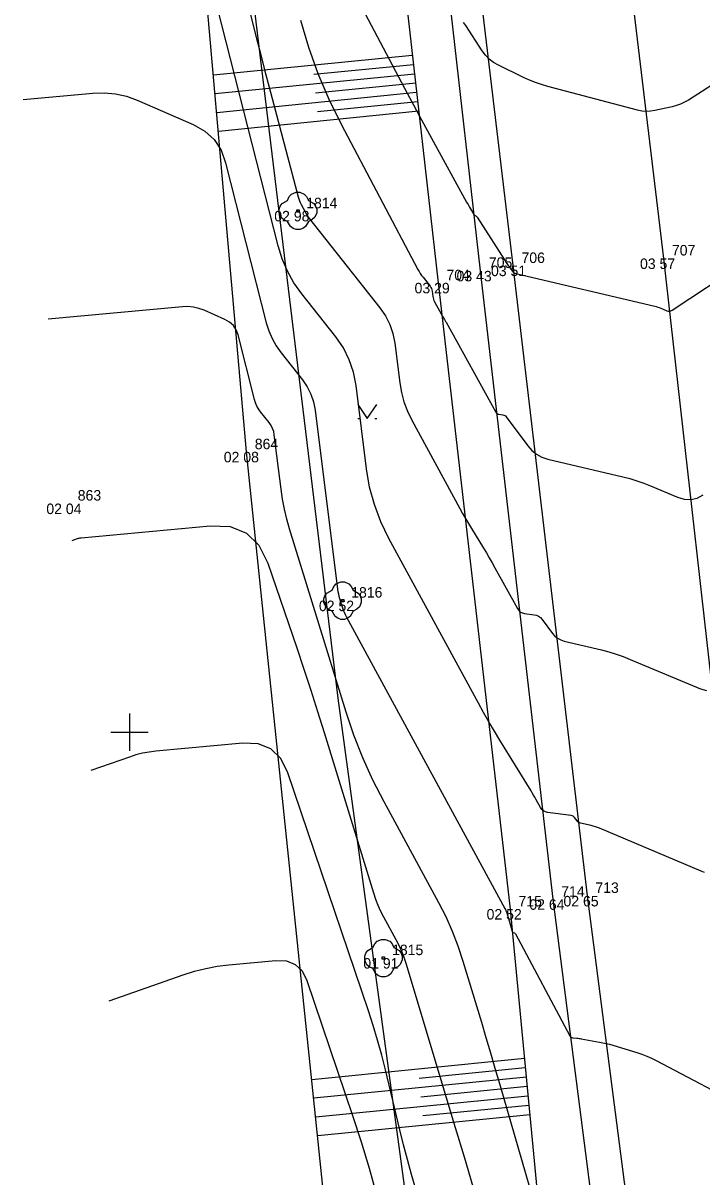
# Model space of a CAD drawing. Extents: x -711234 to -710007, y -1026313 to -1025448.
# Drawn here: x -710902.84 to -710884.74, y -1026086.87 to -1026056.08 of the extents above; entities that cross this region are included whole.
import ezdxf

# ---------------------------------------------------------------- set-up
doc = ezdxf.new("R2010")
doc.units = 0
for name, color, linetype in [('Ex_Major Contours', 7, 'Continuous'), ('Ex_Minor Contours', 7, 'Continuous'), ('Z_body', 7, 'Continuous'), ('Z_body_cisla', 7, 'Continuous'), ('Z_body_vysky_redukovane', 7, 'Continuous'), ('Z_hektometricka_sit', 7, 'Continuous'), ('Z_hrany_paty', 7, 'Continuous'), ('Z_katastr_hranice', 7, 'Continuous'), ('Z_komunikace', 7, 'Continuous'), ('Z_komunikace_osa', 7, 'Continuous'), ('Z_pole_rozhranni', 7, 'Continuous'), ('Z_technicke_srafy', 7, 'Continuous'), ('Z_vdz12_plna', 7, 'Continuous'), ('Z_zelen_jednotliva', 7, 'Continuous'), ('Z_znaky_kultur', 7, 'Continuous')]:
    doc.layers.add(name, color=color, linetype=linetype)

# ---------------------------------------------------------------- blocks, each defined once
blk = doc.blocks.new('POINT_DISPLAY')
blk.add_line((0, 0), (0, 0))
blk = doc.blocks.new('Z24')
for p, q in [((-0.28, 0.28), (-0.23, 0.38)), ((-0.23, 0.38), (-0.17, 0.45)), ((-0.17, 0.45), (-0.05, 0.5)), ((-0.05, 0.5), (0.05, 0.5)), ((0.05, 0.5), (0.17, 0.45)), ((0.17, 0.45), (0.23, 0.38)), ((0.23, 0.38), (0.28, 0.28)), ((-0.5, 0.05), (-0.47, 0.13)), ((-0.5, -0.05), (-0.5, 0.05)), ((-0.47, 0.13), (-0.42, 0.2)), ((-0.42, 0.2), (-0.28, 0.28)), ((-0.03, -0.03), (-0.03, 0.03)), ((-0.03, 0.03), (0.03, 0.03)), ((0.03, 0.03), (0.03, -0.03)), ((0.28, 0.28), (0.42, 0.2)), ((0.42, 0.2), (0.47, 0.13)), ((0.47, 0.13), (0.5, 0.05)), ((0.5, 0.05), (0.5, -0.05)), ((-0.45, -0.17), (-0.5, -0.05)), ((-0.38, -0.23), (-0.45, -0.17)), ((-0.28, -0.28), (-0.38, -0.23)), ((-0.2, -0.42), (-0.28, -0.28)), ((0.03, -0.03), (-0.03, -0.03)), ((0.28, -0.28), (0.2, -0.42)), ((0.38, -0.23), (0.28, -0.28)), ((0.45, -0.17), (0.38, -0.23)), ((0.5, -0.05), (0.45, -0.17)), ((-0.13, -0.47), (-0.2, -0.42)), ((-0.05, -0.5), (-0.13, -0.47)), ((0.05, -0.5), (-0.05, -0.5)), ((0.13, -0.47), (0.05, -0.5)), ((0.2, -0.42), (0.13, -0.47))]:
    blk.add_line(p, q)
blk = doc.blocks.new('Z314')
for p, q in [((-0.25, 0.17), (0, -0.2)), ((0, -0.2), (0.25, 0.17)), ((-0.25, -0.2), (-0.2, -0.2)), ((0.2, -0.2), (0.25, -0.2))]:
    blk.add_line(p, q)

msp = doc.modelspace()

# ---------------------------------------------------------------- linework, layer by layer
at = {"layer": 'Ex_Major Contours'}
for points in [[(-710898.331, -1026049.709), (-710896.61, -1026056.491), (-710896.5, -1026056.925), (-710896.388, -1026057.358), (-710896.275, -1026057.791), (-710896.162, -1026058.224), (-710895.505, -1026060.713), (-710895.489, -1026060.766), (-710895.471, -1026060.818), (-710895.449, -1026060.869), (-710895.425, -1026060.919), (-710895.321, -1026061.116), (-710895.294, -1026061.164), (-710895.264, -1026061.211), (-710895.233, -1026061.257), (-710895.2, -1026061.301), (-710893.325, -1026063.673), (-710893.176, -1026063.889), (-710893.061, -1026064.119), (-710892.978, -1026064.362), (-710892.929, -1026064.619), (-710892.796, -1026065.676), (-710892.752, -1026065.936), (-710892.683, -1026066.189), (-710892.592, -1026066.434), (-710892.476, -1026066.672), (-710891.193, -1026069.034), (-710891.119, -1026069.168), (-710891.043, -1026069.301), (-710890.966, -1026069.434), (-710890.886, -1026069.565), (-710890.565, -1026070.088), (-710890.486, -1026070.219), (-710890.408, -1026070.351), (-710890.331, -1026070.484), (-710890.257, -1026070.618), (-710889.657, -1026071.704), (-710889.621, -1026071.755), (-710889.578, -1026071.794), (-710889.526, -1026071.82), (-710889.465, -1026071.835), (-710889.208, -1026071.869), (-710889.146, -1026071.882), (-710889.092, -1026071.907), (-710889.043, -1026071.943), (-710889.002, -1026071.99), (-710888.724, -1026072.365), (-710888.66, -1026072.438), (-710888.587, -1026072.496), (-710888.504, -1026072.54), (-710888.412, -1026072.57), (-710887.419, -1026072.805), (-710887.223, -1026072.856), (-710887.029, -1026072.915), (-710886.838, -1026072.982), (-710886.649, -1026073.057), (-710884.78, -1026073.844), (-710884.62, -1026073.892)], [(-710901.531, -1026069.883), (-710901.388, -1026069.833), (-710901.364, -1026069.825), (-710901.34, -1026069.819), (-710901.315, -1026069.814), (-710901.291, -1026069.811), (-710897.85, -1026069.492), (-710897.317, -1026069.514), (-710896.883, -1026069.688), (-710896.548, -1026070.013), (-710896.311, -1026070.491), (-710895.543, -1026072.754), (-710895.355, -1026073.317), (-710895.17, -1026073.88), (-710894.99, -1026074.445), (-710894.813, -1026075.011), (-710893.493, -1026079.292), (-710893.438, -1026079.456), (-710893.375, -1026079.616), (-710893.304, -1026079.773), (-710893.226, -1026079.926), (-710892.896, -1026080.533), (-710892.818, -1026080.687), (-710892.748, -1026080.844), (-710892.686, -1026081.004), (-710892.632, -1026081.168), (-710891.315, -1026085.55), (-710891.08, -1026086.336), (-710890.846, -1026087.122)]]:
    msp.add_lwpolyline(points, dxfattribs=at)
at = {"layer": 'Ex_Minor Contours'}
for points in [[(-710884.667, -1026078.749), (-710884.758, -1026078.709), (-710887.471, -1026077.566), (-710887.525, -1026077.545), (-710887.58, -1026077.526), (-710887.635, -1026077.509), (-710887.691, -1026077.494), (-710887.975, -1026077.427), (-710888.001, -1026077.419), (-710888.025, -1026077.406), (-710888.046, -1026077.389), (-710888.064, -1026077.369), (-710888.132, -1026077.277), (-710888.15, -1026077.257), (-710888.171, -1026077.241), (-710888.195, -1026077.23), (-710888.222, -1026077.224), (-710888.853, -1026077.142), (-710888.913, -1026077.127), (-710888.964, -1026077.101), (-710889.007, -1026077.063), (-710889.042, -1026077.013), (-710889.166, -1026076.788), (-710889.197, -1026076.732), (-710889.229, -1026076.677), (-710889.262, -1026076.622), (-710889.295, -1026076.567), (-710890.125, -1026075.216), (-710890.272, -1026074.971), (-710890.417, -1026074.725), (-710890.558, -1026074.477), (-710890.696, -1026074.227), (-710893.085, -1026069.828), (-710893.3, -1026069.386), (-710893.471, -1026068.929), (-710893.598, -1026068.458), (-710893.681, -1026067.973), (-710893.96, -1026065.747), (-710894.028, -1026065.394), (-710894.141, -1026065.061), (-710894.299, -1026064.746), (-710894.503, -1026064.45), (-710895.408, -1026063.306), (-710895.617, -1026063.011), (-710895.792, -1026062.7), (-710895.933, -1026062.371), (-710896.04, -1026062.026), (-710897.768, -1026055.213)], [(-710894.049, -1026055.203), (-710892.59, -1026057.964), (-710892.432, -1026058.262), (-710892.273, -1026058.559), (-710892.112, -1026058.855), (-710891.95, -1026059.151), (-710891.012, -1026060.854), (-710890.994, -1026060.888), (-710890.975, -1026060.921), (-710890.956, -1026060.955), (-710890.936, -1026060.988), (-710890.831, -1026061.168), (-710890.825, -1026061.177), (-710890.818, -1026061.186), (-710890.81, -1026061.193), (-710890.802, -1026061.2), (-710890.765, -1026061.226), (-710890.756, -1026061.233), (-710890.748, -1026061.241), (-710890.741, -1026061.249), (-710890.734, -1026061.258), (-710889.919, -1026062.521), (-710889.904, -1026062.544), (-710889.888, -1026062.567), (-710889.872, -1026062.59), (-710889.856, -1026062.612), (-710889.79, -1026062.701), (-710889.772, -1026062.721), (-710889.752, -1026062.738), (-710889.729, -1026062.75), (-710889.703, -1026062.758), (-710885.998, -1026063.635), (-710885.957, -1026063.645), (-710885.916, -1026063.658), (-710885.876, -1026063.672), (-710885.836, -1026063.687), (-710885.679, -1026063.754), (-710885.64, -1026063.765), (-710885.602, -1026063.767), (-710885.565, -1026063.758), (-710885.529, -1026063.74), (-710883.678, -1026062.513)], [(-710895.441, -1026056.001), (-710895.23, -1026056.719), (-710894.979, -1026057.421), (-710894.688, -1026058.108), (-710894.357, -1026058.78), (-710892.312, -1026062.65), (-710892.281, -1026062.706), (-710892.248, -1026062.759), (-710892.212, -1026062.811), (-710892.174, -1026062.861), (-710891.984, -1026063.101), (-710891.964, -1026063.131), (-710891.948, -1026063.163), (-710891.937, -1026063.196), (-710891.93, -1026063.232), (-710891.912, -1026063.378), (-710891.905, -1026063.414), (-710891.896, -1026063.448), (-710891.883, -1026063.482), (-710891.867, -1026063.515), (-710891.69, -1026063.841), (-710891.68, -1026063.859), (-710891.67, -1026063.878), (-710891.659, -1026063.896), (-710891.648, -1026063.914), (-710891.604, -1026063.986), (-710891.593, -1026064.004), (-710891.582, -1026064.023), (-710891.572, -1026064.041), (-710891.561, -1026064.059), (-710890.234, -1026066.463), (-710890.219, -1026066.485), (-710890.201, -1026066.501), (-710890.179, -1026066.512), (-710890.154, -1026066.518), (-710890.046, -1026066.532), (-710890.021, -1026066.538), (-710889.998, -1026066.548), (-710889.977, -1026066.563), (-710889.96, -1026066.583), (-710889.384, -1026067.361), (-710889.275, -1026067.486), (-710889.149, -1026067.586), (-710889.008, -1026067.662), (-710888.85, -1026067.714), (-710886.85, -1026068.187), (-710886.661, -1026068.235), (-710886.475, -1026068.292), (-710886.291, -1026068.356), (-710886.109, -1026068.428), (-710885.388, -1026068.732), (-710885.21, -1026068.785), (-710885.037, -1026068.792), (-710884.867, -1026068.753), (-710884.702, -1026068.668)], [(-710882.762, -1026056.634), (-710885.098, -1026058.131), (-710885.201, -1026058.19), (-710885.307, -1026058.24), (-710885.417, -1026058.28), (-710885.531, -1026058.311), (-710885.996, -1026058.413), (-710886.113, -1026058.431), (-710886.228, -1026058.436), (-710886.344, -1026058.426), (-710886.459, -1026058.403), (-710888.846, -1026057.769), (-710889.013, -1026057.721), (-710889.177, -1026057.664), (-710889.338, -1026057.6), (-710889.496, -1026057.527), (-710890.166, -1026057.202), (-710890.295, -1026057.128), (-710890.41, -1026057.04), (-710890.512, -1026056.936), (-710890.6, -1026056.817), (-710891.034, -1026056.145), (-710891.064, -1026056.103), (-710891.097, -1026056.065)], [(-710902.837, -1026058.116), (-710900.981, -1026057.946), (-710900.674, -1026057.937), (-710900.374, -1026057.965), (-710900.08, -1026058.032), (-710899.792, -1026058.137), (-710898.306, -1026058.783), (-710897.994, -1026058.959), (-710897.746, -1026059.188), (-710897.56, -1026059.47), (-710897.437, -1026059.805), (-710896.353, -1026064.076), (-710896.286, -1026064.292), (-710896.198, -1026064.498), (-710896.088, -1026064.693), (-710895.957, -1026064.878), (-710895.39, -1026065.596), (-710895.262, -1026065.781), (-710895.163, -1026065.978), (-710895.092, -1026066.187), (-710895.05, -1026066.408), (-710894.452, -1026071.182), (-710894.443, -1026071.245), (-710894.431, -1026071.308), (-710894.416, -1026071.371), (-710894.398, -1026071.433), (-710894.322, -1026071.679), (-710894.302, -1026071.741), (-710894.278, -1026071.8), (-710894.252, -1026071.859), (-710894.223, -1026071.916), (-710889.991, -1026079.708), (-710889.977, -1026079.736), (-710889.964, -1026079.764), (-710889.952, -1026079.793), (-710889.943, -1026079.823), (-710889.906, -1026079.944), (-710889.897, -1026079.974), (-710889.888, -1026080.005), (-710889.879, -1026080.035), (-710889.871, -1026080.065), (-710889.797, -1026080.32), (-710889.793, -1026080.329), (-710889.788, -1026080.336), (-710889.781, -1026080.342), (-710889.773, -1026080.346), (-710889.737, -1026080.359), (-710889.729, -1026080.363), (-710889.722, -1026080.369), (-710889.715, -1026080.375), (-710889.71, -1026080.383), (-710888.263, -1026083.104), (-710888.248, -1026083.125), (-710888.23, -1026083.142), (-710888.208, -1026083.152), (-710888.182, -1026083.157), (-710888.07, -1026083.166), (-710888.043, -1026083.168), (-710888.015, -1026083.171), (-710887.987, -1026083.175), (-710887.96, -1026083.18), (-710887.472, -1026083.269), (-710887.382, -1026083.287), (-710887.292, -1026083.307), (-710887.203, -1026083.33), (-710887.115, -1026083.355), (-710886.478, -1026083.548), (-710886.344, -1026083.592), (-710886.212, -1026083.642), (-710886.083, -1026083.699), (-710885.957, -1026083.762), (-710883.459, -1026085.077)], [(-710889.128, -1026087.826), (-710890.128, -1026084.381), (-710890.247, -1026083.972), (-710890.367, -1026083.563), (-710890.489, -1026083.155), (-710890.611, -1026082.747), (-710891.101, -1026081.116), (-710891.234, -1026080.712), (-710891.386, -1026080.317), (-710891.559, -1026079.93), (-710891.753, -1026079.551), (-710893.215, -1026076.859), (-710893.511, -1026076.28), (-710893.778, -1026075.688), (-710894.015, -1026075.083), (-710894.222, -1026074.466), (-710895.73, -1026069.576), (-710895.805, -1026069.314), (-710895.868, -1026069.049), (-710895.919, -1026068.782), (-710895.959, -1026068.512), (-710896.139, -1026067.07), (-710896.156, -1026066.981), (-710896.185, -1026066.896), (-710896.225, -1026066.816), (-710896.277, -1026066.741), (-710896.506, -1026066.451), (-710896.559, -1026066.376), (-710896.604, -1026066.297), (-710896.64, -1026066.214), (-710896.667, -1026066.126), (-710897.105, -1026064.397), (-710897.155, -1026064.262), (-710897.23, -1026064.147), (-710897.331, -1026064.055), (-710897.457, -1026063.984), (-710898.012, -1026063.742), (-710898.152, -1026063.691), (-710898.295, -1026063.659), (-710898.442, -1026063.645), (-710898.591, -1026063.649), (-710902.17, -1026063.977)], [(-710892.366, -1026087.198), (-710892.482, -1026086.804), (-710892.591, -1026086.408), (-710892.695, -1026086.011), (-710892.793, -1026085.612), (-710893.175, -1026084.014), (-710893.275, -1026083.616), (-710893.384, -1026083.22), (-710893.502, -1026082.827), (-710893.63, -1026082.437), (-710895.792, -1026076.06), (-710895.974, -1026075.693), (-710896.232, -1026075.443), (-710896.566, -1026075.309), (-710896.975, -1026075.293), (-710899.294, -1026075.508), (-710899.475, -1026075.53), (-710899.653, -1026075.563), (-710899.829, -1026075.608), (-710900.002, -1026075.663), (-710901.035, -1026076.027)], [(-710900.54, -1026082.171), (-710898.567, -1026081.475), (-710898.269, -1026081.381), (-710897.966, -1026081.305), (-710897.66, -1026081.247), (-710897.35, -1026081.209), (-710896.1, -1026081.093), (-710895.814, -1026081.105), (-710895.581, -1026081.198), (-710895.401, -1026081.373), (-710895.273, -1026081.629), (-710894.052, -1026085.231), (-710893.823, -1026085.932), (-710893.611, -1026086.639), (-710893.415, -1026087.35)]]:
    msp.add_lwpolyline(points, dxfattribs=at)
at = {"layer": 'Z_hektometricka_sit'}
for p, q in [((-710900, -1026074.5), (-710900, -1026075.5)), ((-710900.5, -1026075), (-710899.5, -1026075))]:
    msp.add_line(p, q, dxfattribs=at)
at = {"layer": 'Z_hrany_paty'}
for p, q in [((-710893.67, -1026046.27), (-710891.77, -1026063.01)), ((-710891.77, -1026063.01), (-710889.85, -1026079.72)), ((-710889.85, -1026079.72), (-710888.32, -1026095.81))]:
    msp.add_line(p, q, dxfattribs=at)
at = {"layer": 'Z_katastr_hranice'}
msp.add_lwpolyline([(-710889.78, -1026108.36), (-710894.44, -1026074.09), (-710896.69, -1026055.45)], dxfattribs=at)
at = {"layer": 'Z_komunikace'}
for p, q in [((-710892.52, -1026046.16), (-710890.65, -1026062.69)), ((-710890.65, -1026062.69), (-710888.71, -1026079.46)), ((-710888.71, -1026079.46), (-710886.65, -1026095.55))]:
    msp.add_line(p, q, dxfattribs=at)
at = {"layer": 'Z_komunikace_osa'}
for p, q in [((-710887.74, -1026045.91), (-710885.76, -1026062.36)), ((-710885.76, -1026062.36), (-710883.93, -1026078.67))]:
    msp.add_line(p, q, dxfattribs=at)
at = {"layer": 'Z_pole_rozhranni'}
for p, q in [((-710896.88, -1026067.52), (-710898.59, -1026048.03)), ((-710894.07, -1026094.55), (-710896.88, -1026067.52))]:
    msp.add_line(p, q, dxfattribs=at)
at = {"layer": 'Z_technicke_srafy'}
for p, q in [((-710892.46, -1026056.94), (-710897.76, -1026057.47)), ((-710892.4, -1026057.44), (-710897.72, -1026057.97)), ((-710892.43, -1026057.19), (-710895.09, -1026057.45)), ((-710892.37, -1026057.68), (-710895.04, -1026057.95)), ((-710892.35, -1026057.93), (-710897.67, -1026058.47)), ((-710892.32, -1026058.18), (-710894.99, -1026058.45)), ((-710892.29, -1026058.43), (-710897.63, -1026058.97)), ((-710889.47, -1026083.71), (-710895.14, -1026084.28)), ((-710889.42, -1026084.21), (-710895.09, -1026084.77)), ((-710889.45, -1026083.96), (-710892.28, -1026084.24)), ((-710889.4, -1026084.46), (-710892.23, -1026084.74)), ((-710889.38, -1026084.71), (-710895.03, -1026085.27)), ((-710889.35, -1026084.96), (-710892.18, -1026085.24)), ((-710889.33, -1026085.21), (-710894.98, -1026085.77))]:
    msp.add_line(p, q, dxfattribs=at)
at = {"layer": 'Z_vdz12_plna'}
for p, q in [((-710891.75, -1026046.11), (-710889.78, -1026062.55)), ((-710889.78, -1026062.55), (-710887.8, -1026079.37)), ((-710887.8, -1026079.37), (-710885.73, -1026095.36))]:
    msp.add_line(p, q, dxfattribs=at)

# ---------------------------------------------------------------- block references
at = {"layer": 'Z_body'}
for p in [(-710895.51, -1026061.09), (-710885.76, -1026062.36), (-710890.65, -1026062.69), (-710889.78, -1026062.55), (-710891.77, -1026063.01), (-710896.88, -1026067.52), (-710901.61, -1026068.9), (-710894.32, -1026071.49), (-710888.71, -1026079.46), (-710887.8, -1026079.37), (-710889.85, -1026079.72), (-710893.23, -1026081.03)]:
    msp.add_blockref('POINT_DISPLAY', p, dxfattribs=at)
at = {"layer": 'Z_zelen_jednotliva'}
for p in [(-710895.51, -1026061.09), (-710894.32, -1026071.49), (-710893.23, -1026081.03)]:
    msp.add_blockref('Z24', p, dxfattribs=at)
at = {"layer": 'Z_znaky_kultur'}
msp.add_blockref('Z314', (-710893.66, -1026066.43), dxfattribs=at)

# ---------------------------------------------------------------- texts
at = {"layer": 'Z_body_cisla'}
for s, p in [('1814', (-710895.29, -1026061.02)), ('707', (-710885.54, -1026062.28)), ('705', (-710890.42, -1026062.61)), ('706', (-710889.55, -1026062.48)), ('704', (-710891.55, -1026062.94)), ('864', (-710896.66, -1026067.45)), ('863', (-710901.38, -1026068.82)), ('1816', (-710894.09, -1026071.41)), ('713', (-710887.58, -1026079.29)), ('714', (-710888.49, -1026079.39)), ('715', (-710889.63, -1026079.65)), ('1815', (-710893, -1026080.95))]:
    msp.add_text(s, height=0.28, dxfattribs=at).set_placement(p)
at = {"layer": 'Z_body_vysky_redukovane'}
for s, p in [('02 98', (-710896.14, -1026061.37)), ('03 57', (-710886.39, -1026062.64)), ('03 43', (-710891.28, -1026062.97)), ('03 51', (-710890.363, -1026062.83)), ('03 29', (-710892.4, -1026063.29)), ('02 08', (-710897.487, -1026067.8)), ('02 04', (-710902.217, -1026069.18)), ('02 52', (-710894.95, -1026071.77)), ('02 64', (-710889.34, -1026079.74)), ('02 65', (-710888.43, -1026079.65)), ('02 52', (-710890.48, -1026080)), ('01 91', (-710893.767, -1026081.31))]:
    msp.add_text(s, height=0.28, dxfattribs=at).set_placement(p)

doc.saveas('drawing.dxf')
